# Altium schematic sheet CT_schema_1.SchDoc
size 522 x 473 mm
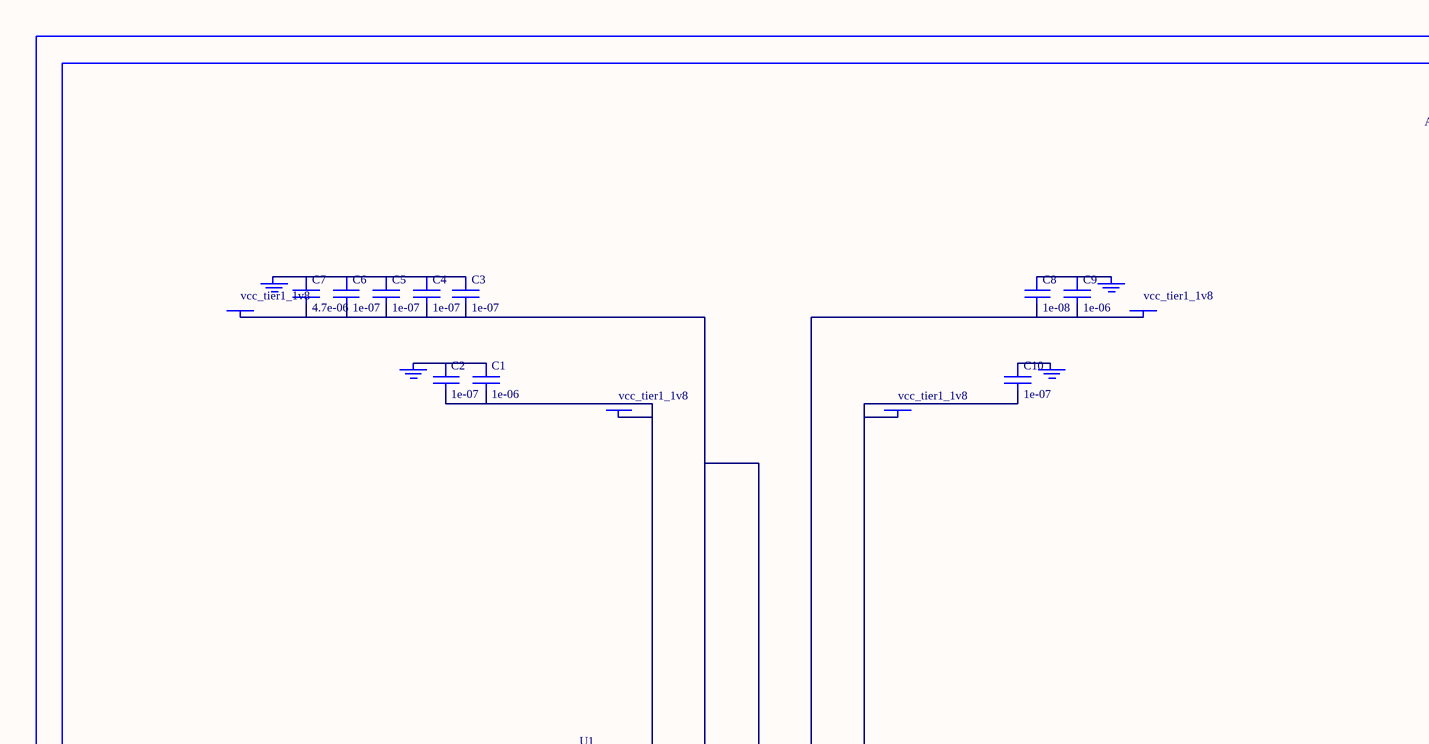
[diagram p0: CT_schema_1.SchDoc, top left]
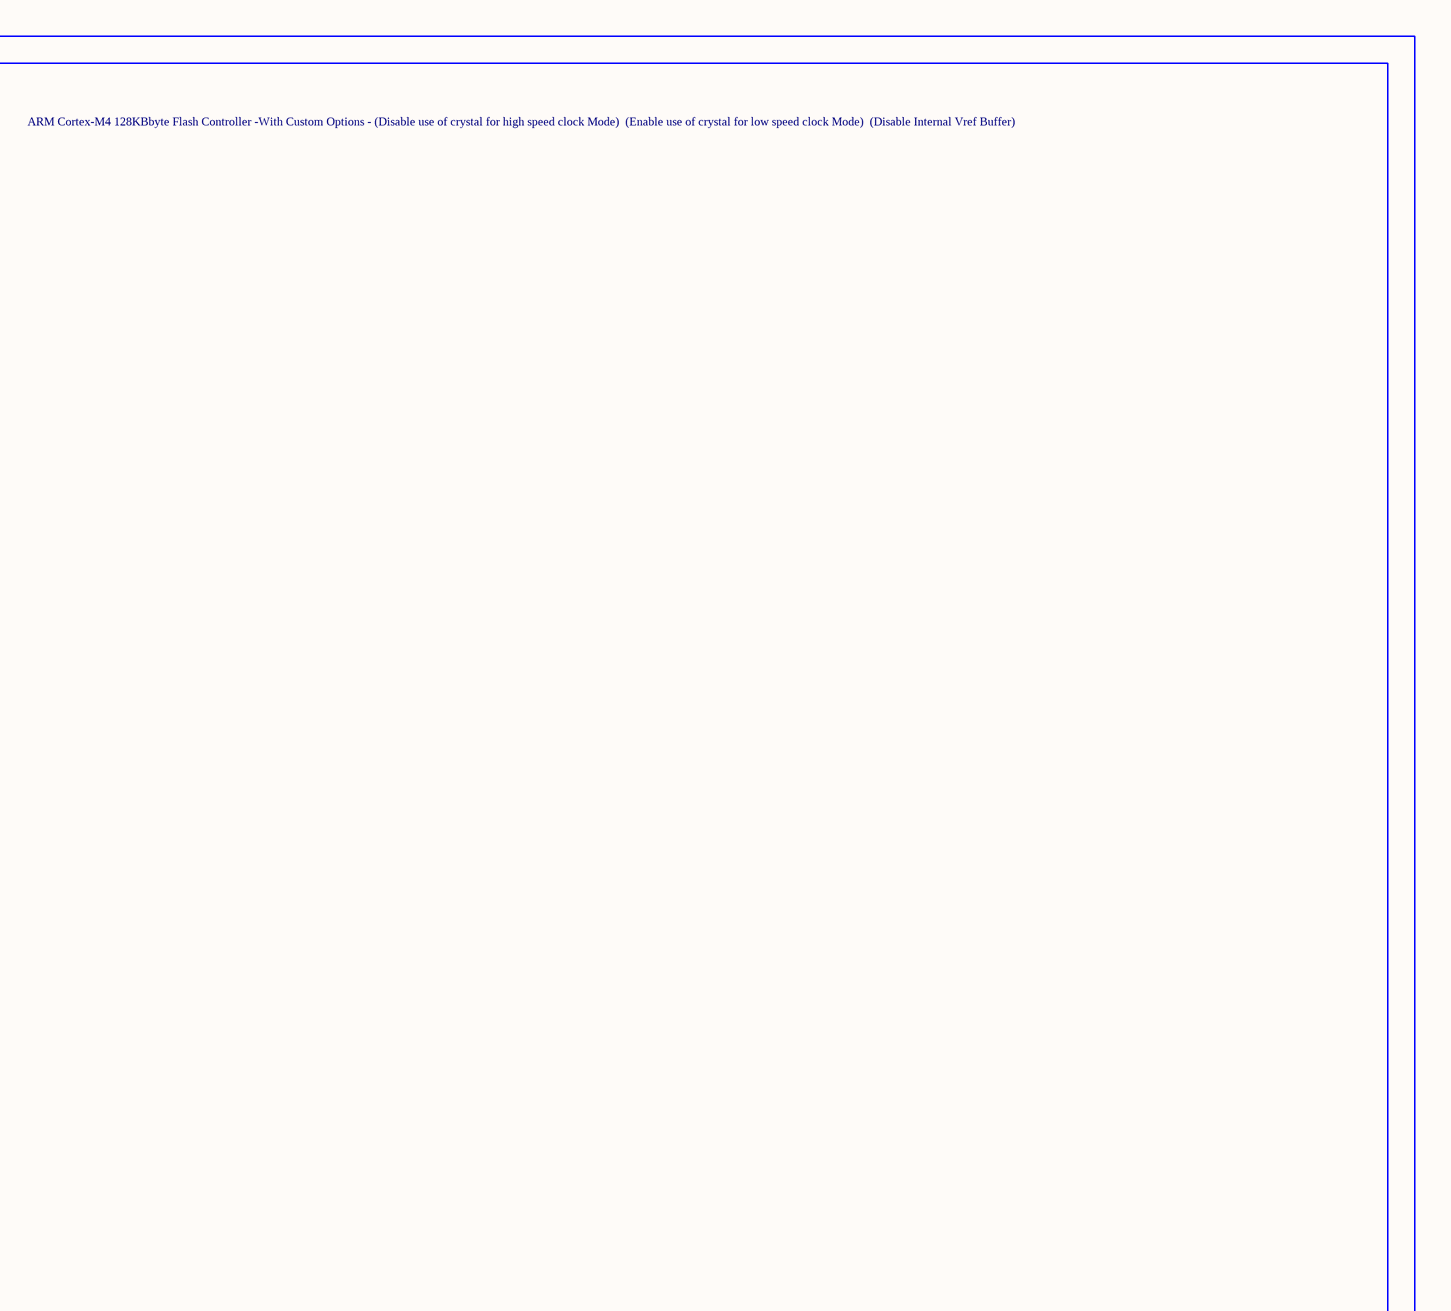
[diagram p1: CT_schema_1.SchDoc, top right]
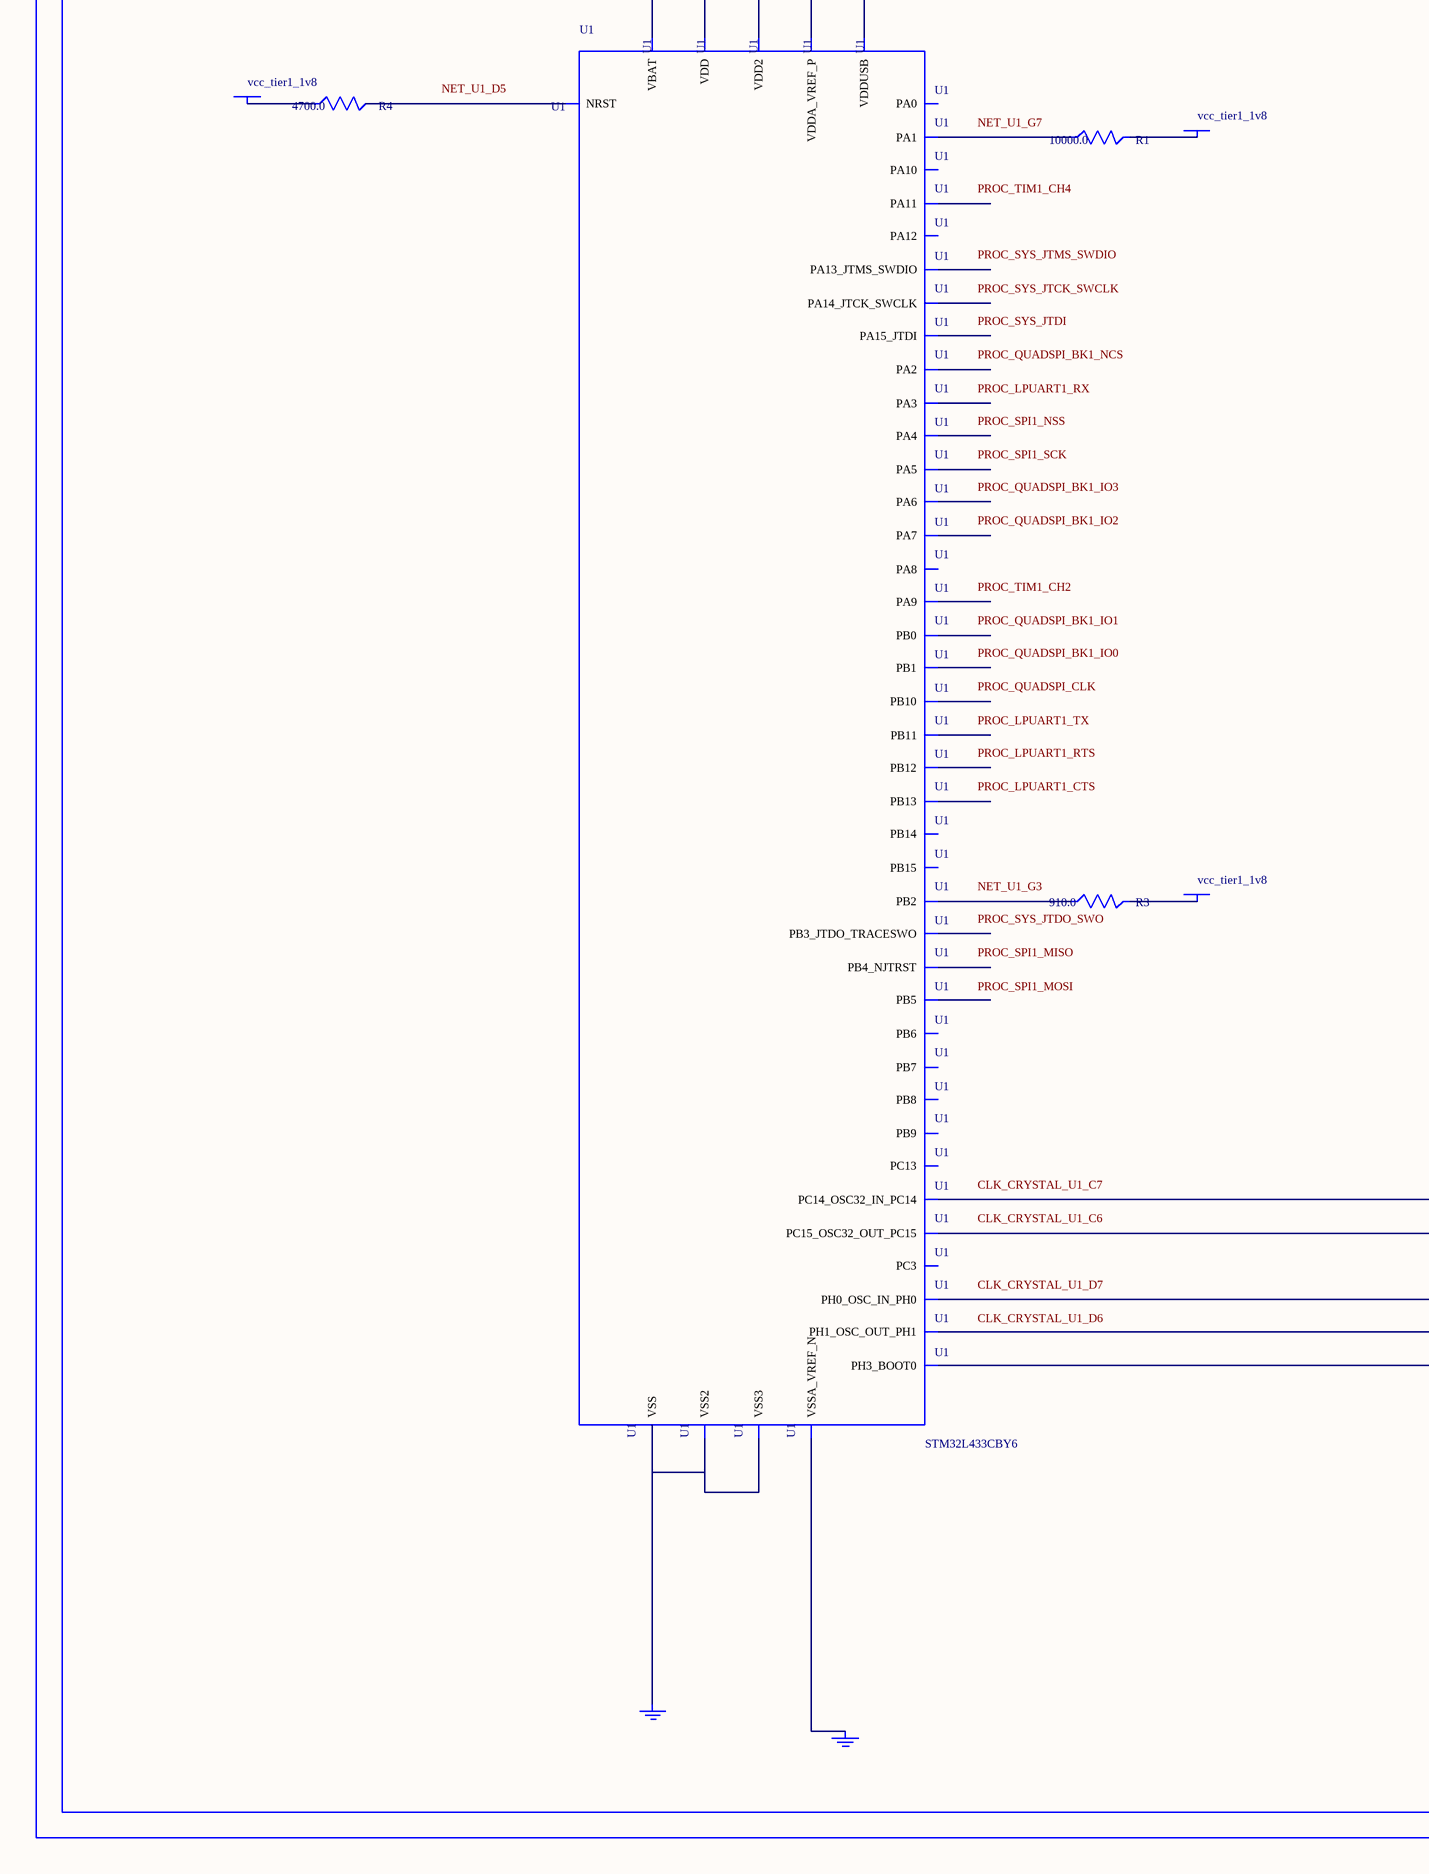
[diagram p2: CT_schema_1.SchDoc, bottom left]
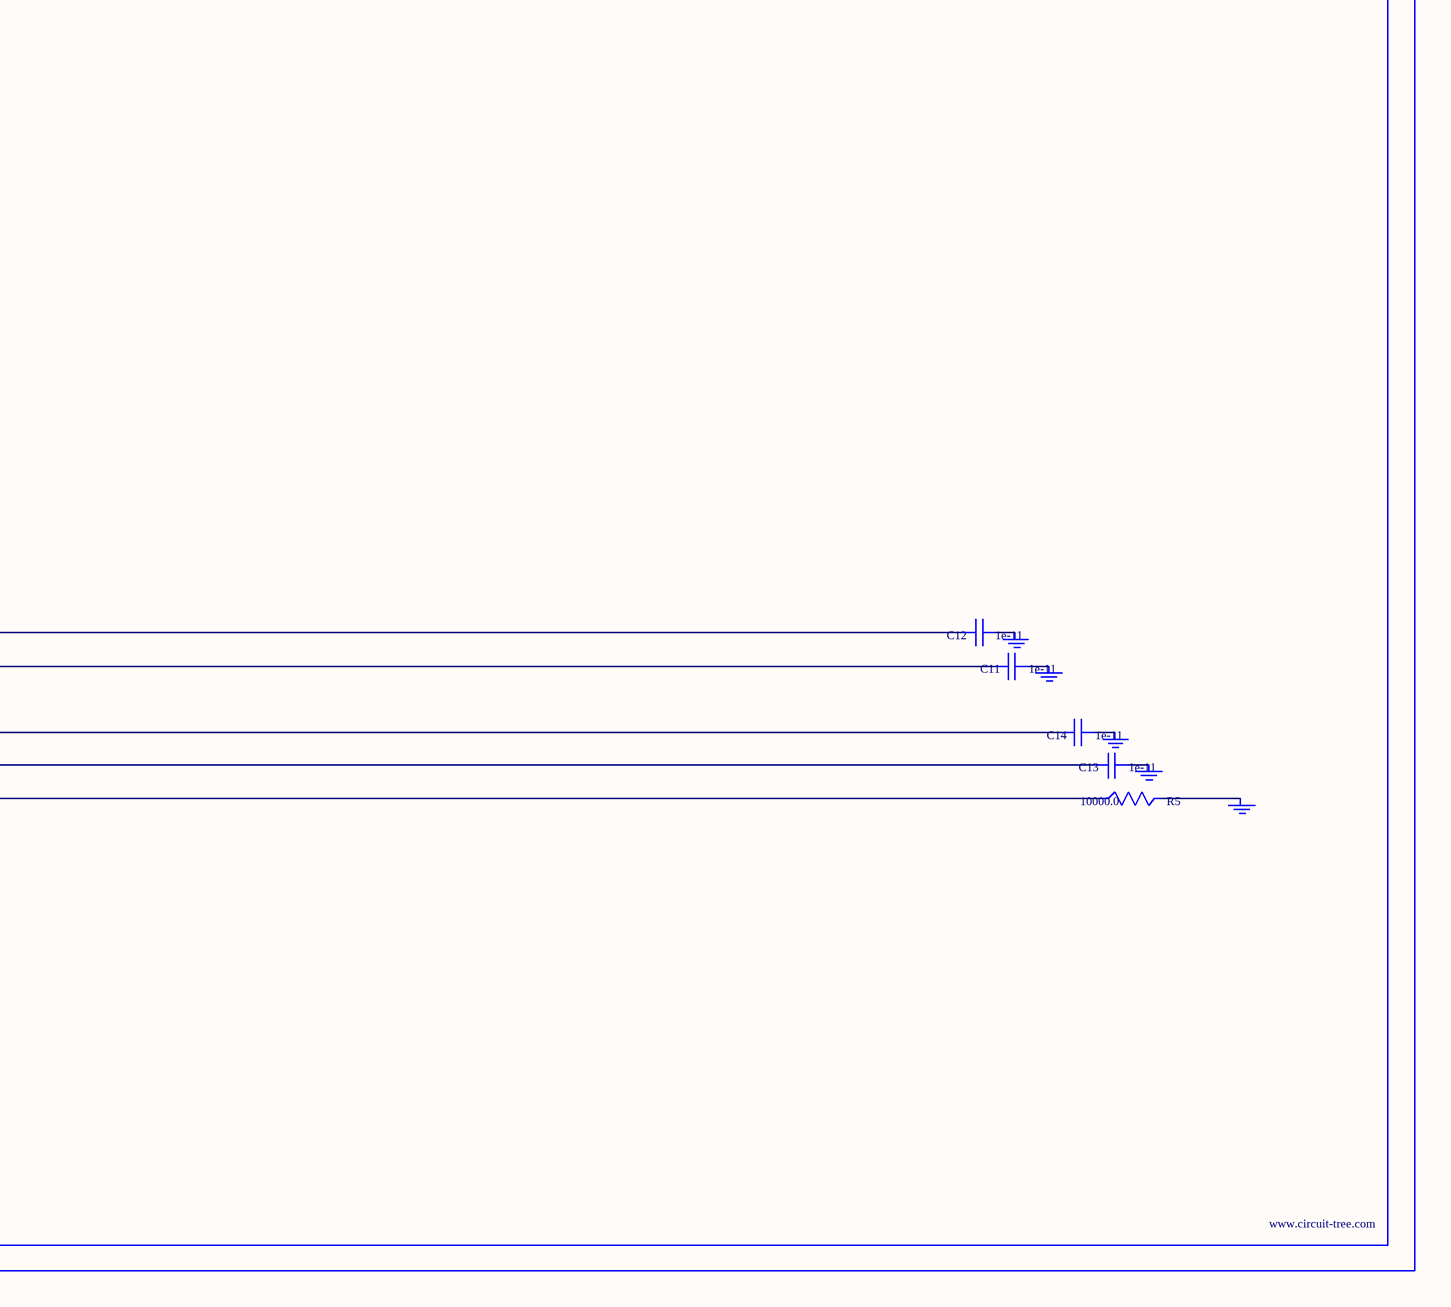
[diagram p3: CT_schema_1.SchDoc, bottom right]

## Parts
BORDER0  (no value)
C1  1e-06  [C0603]
C2  1e-07  [C0603]
C3  1e-07  [C0603]
C4  1e-07  [C0603]
C5  1e-07  [C0603]
C6  1e-07  [C0603]
C7  4.7e-06  [C0603]
C8  1e-08  [C0603]
C9  1e-06  [C0603]
C10  1e-07  [C0603]
C11  1e-11  [C0402]
C12  1e-11  [C0402]
C13  1e-11  [C0402]
C14  1e-11  [C0402]
GND_INSTANCE_0_0  (no value)
GND_INSTANCE_0_1  (no value)
GND_INSTANCE_0_2  (no value)
GND_INSTANCE_0_3  (no value)
GND_INSTANCE_0_4  (no value)
GND_INSTANCE_0_5  (no value)
GND_INSTANCE_0_6  (no value)
GND_INSTANCE_0_7  (no value)
GND_INSTANCE_0_8  (no value)
GND_INSTANCE_0_9  (no value)
GND_INSTANCE_0_10  (no value)
POWER_INSTANCE_0_0  vcc_tier1_1v8
POWER_INSTANCE_0_1  vcc_tier1_1v8
POWER_INSTANCE_0_2  vcc_tier1_1v8
POWER_INSTANCE_0_3  vcc_tier1_1v8
POWER_INSTANCE_0_4  vcc_tier1_1v8
POWER_INSTANCE_0_5  vcc_tier1_1v8
POWER_INSTANCE_0_6  vcc_tier1_1v8
R1  10000.0  [R0603]
R3  910.0  [R0603]
R4  4700.0  [R0603]
R5  10000.0  [R0603]
U1  STM32L433CBY6  [WLCSP49]

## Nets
NetC1_1: C1.1 C2.1 GND_INSTANCE_0_0.0(GND)
NetC1_2: C1.2 C2.2 POWER_INSTANCE_0_0.0(PWR) U1.B6(VBAT)
NetC3_1: C3.1 C4.1 C5.1 C6.1 C7.1 GND_INSTANCE_0_1.0(GND)
NetC3_2: C3.2 C4.2 C5.2 C6.2 C7.2 POWER_INSTANCE_0_1.0(PWR) U1.A7(VDD) U1.G1(VDD2)
NetC8_1: C8.1 C9.1 GND_INSTANCE_0_3.0(GND)
NetC8_2: C8.2 C9.2 POWER_INSTANCE_0_2.0(PWR) U1.F7(VDDA_VREF_P)
NetC10_1: C10.1 GND_INSTANCE_0_4.0(GND)
NetC10_2: C10.2 POWER_INSTANCE_0_3.0(PWR) U1.A1(VDDUSB)
NetC11_1: C11.1 GND_INSTANCE_0_5.0(GND)
NetC11_2: C11.2 U1.C6(PC15_OSC32_OUT_PC15)
NetC12_1: C12.1 GND_INSTANCE_0_6.0(GND)
NetC12_2: C12.2 U1.C7(PC14_OSC32_IN_PC14)
NetC13_1: C13.1 GND_INSTANCE_0_7.0(GND)
NetC13_2: C13.2 U1.D6(PH1_OSC_OUT_PH1)
NetC14_1: C14.1 GND_INSTANCE_0_8.0(GND)
NetC14_2: C14.2 U1.D7(PH0_OSC_IN_PH0)
NetGND_INSTANCE_0_2_0: GND_INSTANCE_0_2.0(GND) R5.2
NetGND_INSTANCE_0_9_0: GND_INSTANCE_0_9.0(GND) U1.E7(VSSA_VREF_N)
NetGND_INSTANCE_0_10_0: GND_INSTANCE_0_10.0(GND) U1.A6(VSS) U1.B1(VSS2) U1.G2(VSS3)
NetPOWER_INSTANCE_0_4_0: POWER_INSTANCE_0_4.0(PWR) R4.1
NetPOWER_INSTANCE_0_5_0: POWER_INSTANCE_0_5.0(PWR) R1.2
NetPOWER_INSTANCE_0_6_0: POWER_INSTANCE_0_6.0(PWR) R3.2
NetR1_1: R1.1 U1.G7(PA1)
NetR3_1: R3.1 U1.G3(PB2)
NetR4_2: R4.2 U1.D5(NRST)
NetR5_1: R5.1 U1.A5(PH3_BOOT0)

Not connected (* = marked no-connect by the designer): U1 A2(PA14_JTCK_SWCLK) A3(PB3_JTDO_TRACESWO) A4(PB4_NJTRST) B2(PA13_JTMS_SWDIO) B3(PA15_JTDI) B4(PB5) B5(PB8) B7(PC13) C1(PA11) C2(PA10) C3(PA12) C4(PB6) C5(PB9) D1(PA8) D2(PA9) D3(PB15) D4(PB7) E1(PB14) E2(PB13) E3(PB10) E4(PA3) E5(PA2) E6(PC3) F1(PB12) F2(PB11) F3(PA7) F4(PA6) F5(PA5) F6(PA0) G4(PB1) G5(PB0) G6(PA4)

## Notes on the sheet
- Labels drawn without touching a wire or pin: CLK_CRYSTAL_U1_C6, CLK_CRYSTAL_U1_C7, CLK_CRYSTAL_U1_D6, CLK_CRYSTAL_U1_D7, NET_U1_D5, NET_U1_G3, NET_U1_G7, PROC_LPUART1_CTS, PROC_LPUART1_RTS, PROC_LPUART1_RX, PROC_LPUART1_TX, PROC_QUADSPI_BK1_IO0, PROC_QUADSPI_BK1_IO1, PROC_QUADSPI_BK1_IO2, PROC_QUADSPI_BK1_IO3, PROC_QUADSPI_BK1_NCS, PROC_QUADSPI_CLK, PROC_SPI1_MISO, PROC_SPI1_MOSI, PROC_SPI1_NSS, PROC_SPI1_SCK, PROC_SYS_JTCK_SWCLK, PROC_SYS_JTDI, PROC_SYS_JTDO_SWO, PROC_SYS_JTMS_SWDIO, PROC_TIM1_CH2, PROC_TIM1_CH4

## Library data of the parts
BORDER0 = BORDER_PAGE0
C1 C9 = C0603C105K3RACTU
C2-C6 C10 = 06035C104K4Z2A
C7 = GRM188R6YA475KE15D
C8 = 06035C103K4Z2A
C11-C14 = C0402C100K3GACTU
GND_INSTANCE_0_0-GND_INSTANCE_0_10 = GND
POWER_INSTANCE_0_0-POWER_INSTANCE_0_6 = PWR
R1 R5 = RC0603JR-0710KL
R3 = RC0603JR-07910RL
R4 = RC0603JR-074K7L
